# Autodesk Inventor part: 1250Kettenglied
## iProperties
Category: PARTsolutions
Created: 2011-08
Part Number: 1250Kettenglied
Catalog Web Link: www.cadenas.de
Description: 1250 Kettenglied - Kettenglied
Document SubType Name: Modeling
Designer: PARTsolutions
Density: 1 g/cm^3
Mass: 85.2859 g
Surface Area: 537.346 cm^2
Volume: 85.2859 cm^3
NB: 1250Kettenglied
NN: 1250 Kettenglied
NT: Kettenglied
NBSYN: 1250Kettenglied
LINA: 1250Kettenglied
BEST: 1250Kettenglied
KT: DUMMY
SUPPLIER: Kabelschlepp
ARTICLENO: 1250Kettenglied
BOMINFO: 1250Kettenglied
CREATOR: CADENAS GmbH
PSOL_IDENT_0: {\\10.0.0.251\ps_data\23d-libs\kabelschlepp\4_eketten_st\parts\1250_kettenglied.prj},182 {VTYP=3D},{
PSOL_IDENT_1: NB=1250Kettenglied},{LINA=1250Kettenglied},{NN=1250 Kettenglied},{DATE=31.05.2007 07:52:20},{GEOMDAT
PSOL_IDENT_2: E=18.01.2007 11:42:00},{VERSION=},{LINEID=10},{LINESUBID=-1},{WBVAR=}  {NB=1250Kettenglied},{LINA=12
PSOL_IDENT_3: 50Kettenglied},{KT=DUMMY},{BEST=1250Kettenglied}
Title: 1250Kettenglied
Author: Cadenas PARTsolutions
Comments: Kettenglied
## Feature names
1. Extrusion1
2. Revolution1
3. Revolution2
4. Revolution3
5. Revolution4
6. Revolution5
7. Revolution6
8. Revolution7
